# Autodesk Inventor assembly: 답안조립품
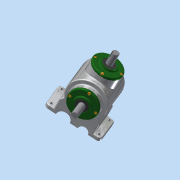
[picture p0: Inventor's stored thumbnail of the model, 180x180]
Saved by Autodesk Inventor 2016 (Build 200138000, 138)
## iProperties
Created: 2018-08
Part Number: 답안조립품
Material: 일반
Document SubType Name: Assembly
Designer: 605-08
Author: 605-08
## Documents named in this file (14)
- C:\Users\605-08\Desktop\480807V1026\답안조립품.iam
- C:\Users\605-08\Desktop\480807V1026\본체.ipt
- C:\Users\605-08\Desktop\480807V1026\메인 베벨기어.ipt
- C:\Users\605-08\Desktop\480807V1026\서브 베벨기어.ipt
- C:\Users\605-08\Desktop\480807V1026\메인 축.ipt
- 메인 축.ipt
- C:\Users\605-08\Desktop\480807V1026\베어링 6203.ipt
- C:\Users\605-08\Desktop\480807V1026\볼트 M4.ipt
- C:\Users\605-08\Desktop\480807V1026\오일실 17 32 8.ipt
- C:\Users\605-08\Desktop\480807V1026\커버.ipt
- C:\Users\605-08\Desktop\480807V1026\키 5x5.ipt
- C:\Users\605-08\Desktop\480807V1026\서브 축.ipt
- 서브 축.ipt
- C:\Users\605-08\Desktop\480807V1026\키 4x4.ipt
